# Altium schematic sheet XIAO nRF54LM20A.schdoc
size 400 x 277 mm; Device: default420x297; Symbol: default420x297; Name: default420x297; Size: "A3"; Id: /; File: XIAO nRF54LM20A; Sheet: /
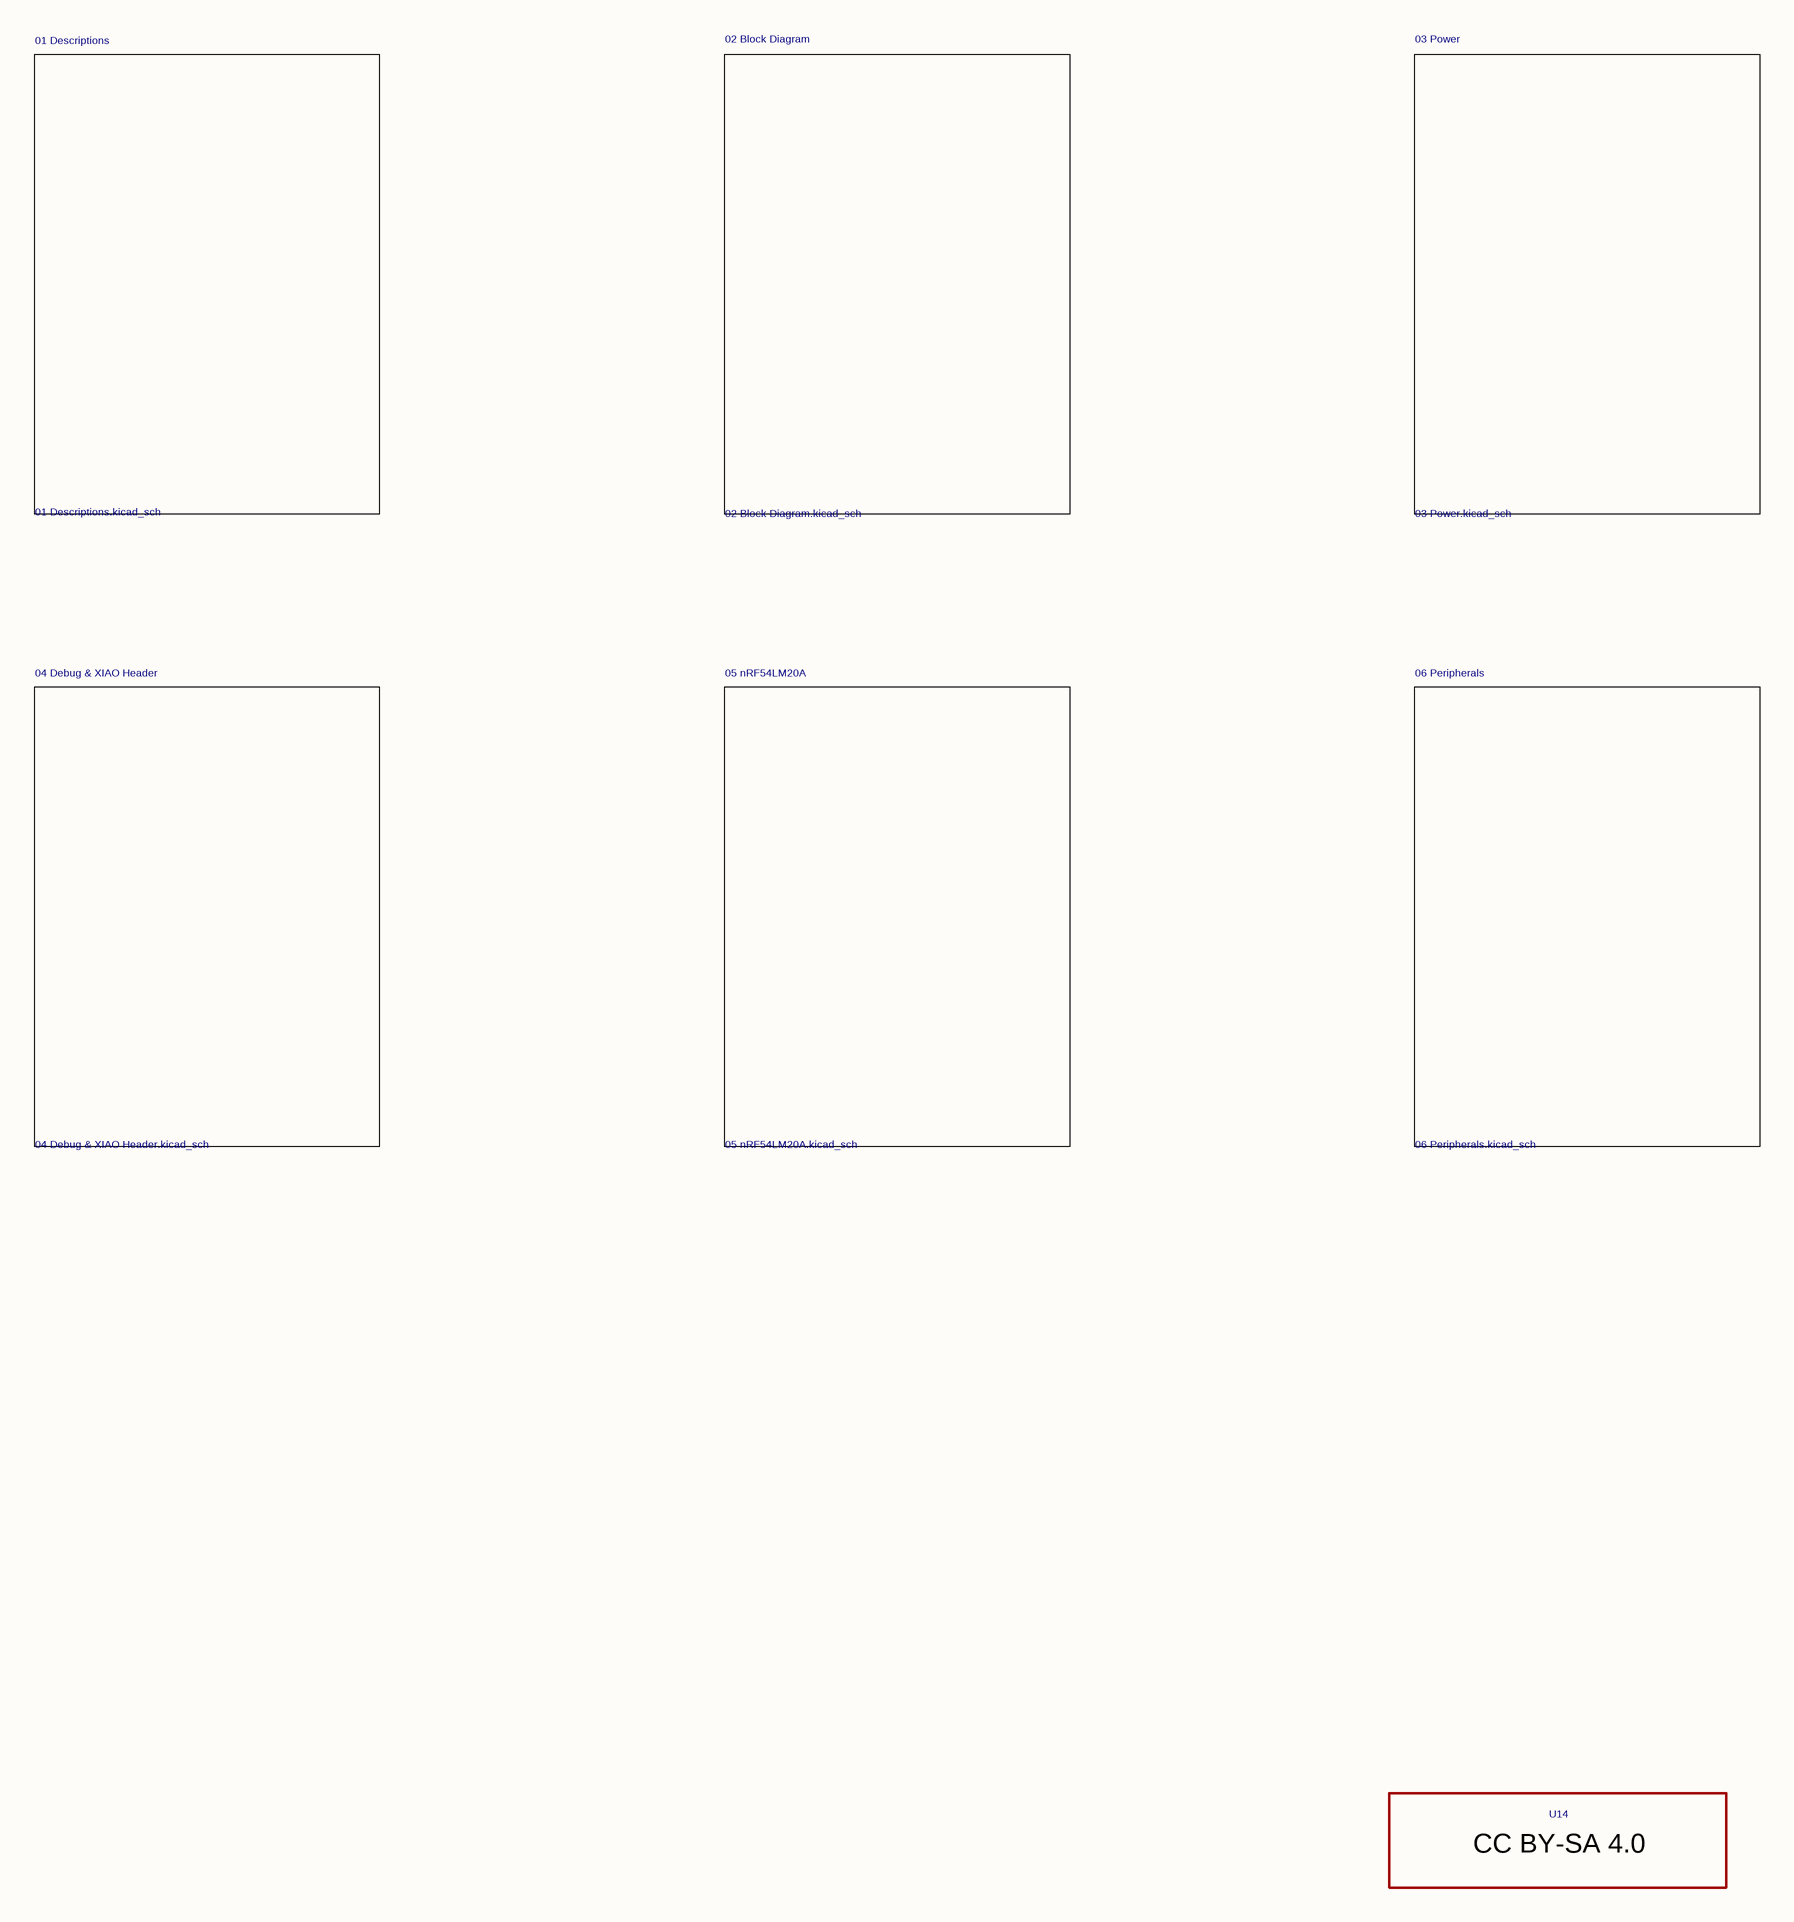
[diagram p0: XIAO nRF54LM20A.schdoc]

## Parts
U14  Misc_LOGO_CC_BY-SA_4.0  [Misc:LOGO_CC_BY-SA_4.0]  (value not drawn)

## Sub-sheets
CBB? = 04 Debug & XIAO Header.schdoc: no entries  | Symbol: 04 Debug & XIAO Header; Sheetname: 04 Debug & XIAO Header; Sheetfile: 04 Debug & XIAO Header.kicad_sch
CBB? = 02 Block Diagram.schdoc: no entries  | Symbol: 02 Block Diagram; Sheetname: 02 Block Diagram; Sheetfile: 02 Block Diagram.kicad_sch
CBB? = 03 Power.schdoc: no entries  | Symbol: 03 Power; Sheetname: 03 Power; Sheetfile: 03 Power.kicad_sch
CBB? = 01 Descriptions.schdoc: no entries  | Symbol: 01 Descriptions; Sheetname: 01 Descriptions; Sheetfile: 01 Descriptions.kicad_sch
CBB? = 06 Peripherals.schdoc: no entries  | Symbol: 06 Peripherals; Sheetname: 06 Peripherals; Sheetfile: 06 Peripherals.kicad_sch
CBB? = 05 nRF54LM20A.schdoc: no entries  | Symbol: 05 nRF54LM20A; Sheetname: 05 nRF54LM20A; Sheetfile: 05 nRF54LM20A.kicad_sch

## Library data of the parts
U14 = Misc_LOGO_CC_BY-SA_4.0: UniqueId: 8791d75d94e1481b; AddInBom: yes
